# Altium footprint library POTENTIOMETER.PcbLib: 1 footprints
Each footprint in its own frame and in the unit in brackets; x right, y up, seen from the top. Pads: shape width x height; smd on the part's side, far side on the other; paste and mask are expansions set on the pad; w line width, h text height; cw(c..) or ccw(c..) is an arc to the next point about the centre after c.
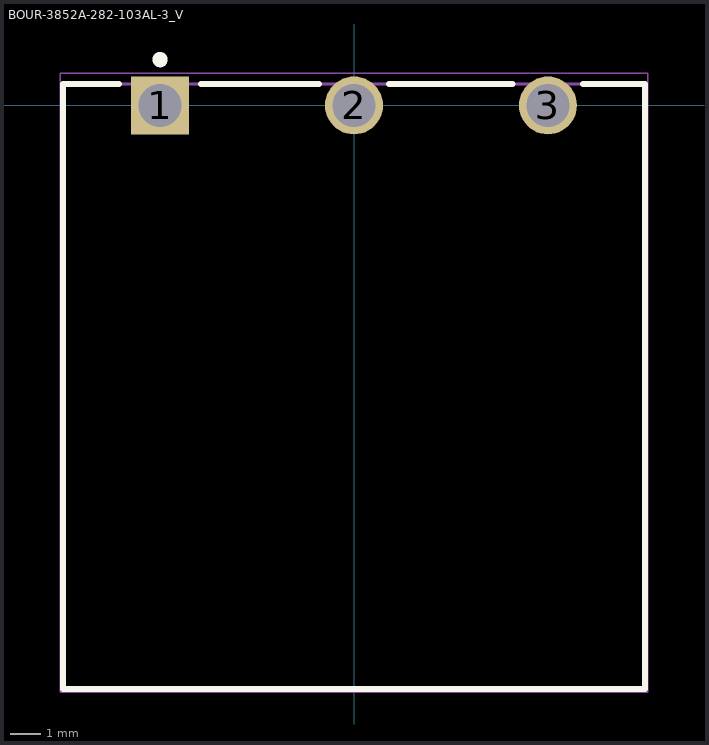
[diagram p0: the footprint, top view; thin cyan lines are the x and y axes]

## BOUR-3852A-282-103AL-3_V [mm] "TH, 3-Leads, Body 19.81x19.05mm, Pitch 6.35mm"
height 9.525
pads (3):
  rect 1.9x1.9 hole 1.4: 1(-6.35,0)
  round 1.9 hole 1.4: 2(0,0) 3(6.35,0)
Top Overlay:
  circle w0.25: c-6.35,1.5 r0.125
  lines w0.2: -7.7,0.7 -9.525,0.7 -9.525,-19.11 9.525,-19.11 9.525,0.7 7.505,0.7 ; -5,0.7 -1.155,0.7 ; 1.155,0.7 5.195,0.7
Mechanical 13:
  lines w0.1: -9.525,-19.11 9.525,-19.11 9.525,0.7 -9.525,0.7 -9.525,-19.11
Mechanical 15:
  lines w0.05: -9.625,-19.21 -9.625,1.05 9.625,1.05 9.625,-19.21 -9.625,-19.21
  lines w0.1: -0.5,0 0.5,0 ; 0,-0.5 0,0.5
3D body: height 12.7, standoff 6.35, extent -3.174,-19.11 3.174,-15.94
3D body: height 15.62, standoff 3.43, extent -6.093,-15.94 6.093,-6.41
3D body: height 19.05, standoff 0, extent -9.522,-6.41 9.522,0.7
